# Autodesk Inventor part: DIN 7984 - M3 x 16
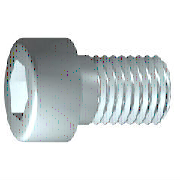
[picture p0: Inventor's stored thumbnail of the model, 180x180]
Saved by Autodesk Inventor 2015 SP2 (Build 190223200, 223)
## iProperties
IsCustomPart: 0
Created: 2012-02
Part Number: DIN 7984 - M3 x 16
Material: Steel, Mild
Description: Cylinder Head Cap Screw
Document SubType Name: Modeling
Standard: DIN 7984
Designer: rYan
Standard Revision: 1985
Standards Organization: DIN
Language: en-US
Size Designation: M3 x 16
Categories: <MemberInstance><Categories><Category DisplayName="Fasteners" InternalName="e4da775c-781d-43d5-af7c-5136215cf5a6" Mnemonic="FSTN"><Category DisplayName="Bolts"
Density: 7.85 g/cm^3
Mass: 1.20728 g
Surface Area: 2.39725 cm^2
Volume: 0.153794 cm^3
Appearance: Halbpoliert
Author: rYan
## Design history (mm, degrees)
sketch "Sketch1"
  geometry: L1 (0.167, 0)-(16, 0); L2 (16, 0)-(16, 1.5); L3 (16, 1.5)-(1.5, 1.5); L4 (1.5, 1.5)-(1.193, 1.5); L5 (1.193, 1.5)-(0, 1.5); L6 (0, 1.5)-(0, 2.75); L7 (0, 2.75)-(-2, 2.75); L8 (-2, 2.75)-(-2, 1.155); L9 (-2, 1.155)-(-0.5, 1.155); L10 (-0.5, 1.155)-(0.167, 0); L11 (-5.6, 0)-(19.6, 0) reference; L12 (0, -0.55)-(0, 3.3) reference; L13 (1.5, 1.5)-(0, 1.5)
  constraints: 22 end point, 6 parallel, 2 collinear, 2 perpendicular, 1 horizontal, 1 point on line
  dimensions: "d1" = 14.5 distance from line of L3.end L2 (= GEL); "d2" = 0.30683 distance of L4.end L3.end (computed from GAL); "d3" = 2 distance between parallel lines of L8 L6 (= KOH); "d4" = 1.5 distance of L8.end L9.end (= INTI); "d5" = 60 deg angle of L10 L1; "d6" = 3 diameter of L3 L1 (= GD); "d7" = 3 diameter of L5 L1 (= BDM); "d8" = 2.3094 diameter of L9 L1 (= 1.1547 x SW); "d9" = 5.5 diameter of L7 L1 (= KOD); "d26" = 16 distance between parallel lines of L12 L2 (= NLG)
revolve "Body" sketch "Sketch1" stored, may be unused: angle "d10" = 90 deg
sketch "Sketch2"
  geometry: L1 (0, -3.85)-(0, 3.85) reference; L2 (-3.85, 0)-(3.85, 0) reference; L3 (1.155, 0)-(0.577, -1); L4 (0.577, -1)-(-0.577, -1); L5 (-0.577, -1)-(-1.155, 0); L6 (-1.155, 0)-(-0.577, 1); L7 (-0.577, 1)-(0.577, 1); L8 (0.577, 1)-(1.155, 0); 2 further points
  constraints: 12 end point, 1 coincident, 1 horizontal alignment, 1 point on line, 12 other
extrude "Slot" join sketch "Sketch2" stored distance "d11" = 10; taper "d12" = 0 deg
fillet "Fillet1" dims "d17" = 0.3 (= RR)
feature "Thread" dims "d13" = 14.5 (= GEL), "d14" = 0
chamfer "Chamfer1" distance "d15" = 0.30673 (= -0.5 x SPD + 0.5 x GD); stored, may be unused: second distance "d16" = 0.30673 (= GUL), angle "d27" = 45 deg
workplane "Work Plane1"
fillet "Fillet2" dims "d30" = 0.1 (= R)
body "Solid1"
other parameters: "GD" = 3 (= NND) [user parameter; used in 2 equation terms], "NLG" = 16 [user parameter; used in 1 equation term], "GEL" = 14.5 [user parameter; used in 2 equation terms], "KOD" = 5.5 [user parameter; used in 1 equation term], "KOH" = 2 [user parameter; used in 1 equation term], "INTI" = 1.5 [user parameter; used in 1 equation term], "GAL" = 0.30673 (= 0.61345 x PTC) [user parameter; used in 1 equation term], "GUL" = 0.30673 (= 0.61345 x PTC) [user parameter; used in 1 equation term], "BDM" = 3 (= NND) [user parameter; used in 1 equation term], "SW" = 2 [user parameter; used in 2 equation terms], "RR" = 0.3 [user parameter; used in 1 equation term], "SPD" = 2.38655 (= NND - 1.2269 x PTC) [user parameter; used in 1 equation term], "d19" = 0, "d28" = 0, "d29" = 0, "R" = 0.1 [user parameter; used in 1 equation term], "TOA" = 30 deg [user parameter], "GD1" = 2.38655 (= THREADDIA - 1.2269 x PTC) [user parameter], "THREADDIA" = 3 [user parameter; used in 1 equation term], "FAWI" = 45 deg [user parameter], "ANG" = 120 deg [user parameter], "PTC" = 0.5 [user parameter; used in 5 equation terms], "NND" = 3 [user parameter; used in 3 equation terms], "E0" = 2.31 (= 1.155 x SW) [user parameter]
